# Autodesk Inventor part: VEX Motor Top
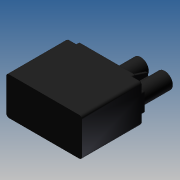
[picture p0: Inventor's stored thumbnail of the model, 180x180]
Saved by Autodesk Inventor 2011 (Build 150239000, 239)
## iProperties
Created: 2010-06
Part Number: VEX Motor Top
Document SubType Name: Modeling
Designer: Phil
Density: 1 g/cm^3
Author: Phil
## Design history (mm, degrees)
sketch "Sketch1"
  geometry: L1 (0, 20)-(37, 20); L2 (0, 0)-(37, 0); L3 (-1.5, 18.5)-(-1.5, 1.5); L4 (38.5, 1.5)-(38.5, 18.5); A1 r 1.5 centre (0, 18.5) between (0, 20) and (-1.5, 18.5); A2 r 1.5 centre (0, 1.5) between (-1.5, 1.5) and (0, 0); A3 r 1.5 centre (37, 1.5) between (37, 0) and (38.5, 1.5); A4 r 1.5 centre (37, 18.5) between (38.5, 18.5) and (37, 20); 2 further points
  constraints: 8 end point, 8 point on circle, 4 centre point
extrude "Extrusion1" new body sketch "Sketch1" distance "d0" = 33.4772; taper "d1" = 0 deg
sketch "Sketch2"
  geometry: L1 (-33.5, 2.5)-(-33.5, 0.5); L2 (-28, 4)-(-27.3, 4); L3 (-29.295, 9.35)-(-28.3, 9.35); L4 (-28.3, 4.315)-(-28.3, 9.35); L5 (-27, 9.35)-(-27, 4.315); L6 (-28.3, 10.65)-(-29.295, 10.65); L7 (-27, 9.35)-(-26.005, 9.35); L8 (-26.005, 10.65)-(-27, 10.65); L9 (-28.3, 10.65)-(-28.3, 15.685); L10 (-27.3, 16)-(-28, 16); L11 (-33.5, 0.5)-(-3.5, 0.5); L12 (-33.5, 19.5)-(-3.5, 19.5); L13 (-27, 15.685)-(-27, 10.65); L14 (-33.5, 20)-(-33.5, 17.5); L15 (-38, 5)-(-36, 5); L16 (-38, 7.438)-(-38, 5); L17 (-38, 15)-(-38, 12.562); L18 (-36, 15)-(-38.5, 15); L19 (-3.5, 0.5)-(-3.5, 2.5); L20 (-3.5, 17.5)-(-3.5, 19.5); L21 (-1, 5)-(1, 5); L22 (1, 5)-(1, 15); L23 (1, 15)-(-1, 15); L24 (-33.5, 20)-(-37, 20); L25 (-38.5, 18.5)-(-38.5, 15); C1 r 6.75 at (-8.6, 10); A1 r 1.5 centre (-37, 18.5) between (-37, 20) and (-38.5, 18.5); 2 further points
  constraints: 50 end point, 2 centre point, 2 point on circle, 2 point on line, 2 tangent, 1 parallel, 1 perpendicular, 29 other
extrude "Extrusion2" cut sketch "Sketch2" distance "d2" = 1.4986; taper "d3" = 0 deg
fillet "Fillet1" dims "d4" = 0.762
workplane "Work Plane1"
mirror "Mirror1"
workplane "Work Plane2"
mirror "Mirror2"
fillet "Fillet2" dims "d5" = 0.508
fillet "Fillet3" dims "d6" = 0.762
workplane "Work Plane4"
sketch "Sketch3"
  geometry: L1 (-38.5, 14.238)-(-38.5, 5.762) reference; L2 (-37.992, 5.762)-(-37.992, 14.238) reference; C1 r 4.255 at (-33.737, 10); C2 r 4.255 at (-21.037, 10); 2 further points
  constraints: 2 centre point, 2 horizontal alignment, 1 equal radius, 1 midpoint, 1 tangent
  dimensions: "d9" = 8.509 diameter of C1; "d10" = 12.7 distance of C2.centre C1.centre
extrude "Extrusion3" join sketch "Sketch3" stored distance "d11" = 9.525; taper "d12" = 0 deg
workplane "Work Plane5"
sketch "Sketch4"
  geometry: L1 (33.477, 16)-(33.477, 12.738) reference; L2 (33.477, 4.262)-(33.477, 1) reference; L3 (33.477, 14.494)-(45.466, 10.648); L4 (45.466, 10.648)-(45.466, 6.352); L5 (45.466, 6.352)-(33.477, 2.506); L6 (33.477, 14.494)-(33.477, 2.506); L7 (48.489, 12.755)-(48.489, 4.246) reference; 3 further points
  constraints: 8 end point, 2 midpoint, 2 parallel, 2 point on line, 1 horizontal alignment
  dimensions: "d14" = 11.9888 distance of L5.end L3.start; "d15" = 72.21 deg angle of L2 L5; "d16" = 72.21 deg angle of L1 L3; "d17" = 11.9888 distance between parallel lines of L6 L4
extrude "Extrusion4" join sketch "Sketch4" stored distance "d18" = 1.27; taper "d19" = 0 deg
sketch "Sketch5"
  geometry: L1 (0, 4.295)-(1.27, 4.295) reference; L2 (-1.46, 2.148)-(2.731, 2.148); 3 further points
  constraints: 2 end point, 2 horizontal alignment, 1 parallel, 2 other
feature "Rib1" sketch "Sketch5" dims "d20" = 1.27, "d21" = 2.54, "d22" = 0
fillet "Fillet4" dims "d23" = 0.508
fillet "Fillet5" dims "d24" = 0.254
sketch "Sketch6"
  geometry: C1 r 4.255 at (0, 0) reference; C2 r 4.255 at (12.7, 0) reference; 1 further point
hole "Hole1" sketch "Sketch6" at (0, 0), (12.7, 0) diameter "d25" = 5.5118; stored, may be unused: countersink angle "d29" = 82 deg, drill point angle "d31" = 118 deg; dims "d26" = 19.05, "d27" = 9.525, "d28" = 6.35, "d30" = 12.7
sketch "Sketch7"
  geometry: L1 (1.5, 5.762)-(1.5, 14.238) reference; C1 r 6.744 at (-8.609, 10); 1 further point
  constraints: 1 centre point
  dimensions: "d32" = 10.1092 distance from line of L1 C1.centre; "d33" = 13.4874 diameter of C1
extrude "Extrusion5" join sketch "Sketch7" distance "d34" = 1.5875; taper "d35" = -25 deg
sketch "Sketch8"
  geometry: 2 further points
hole "Hole2" sketch "Sketch8" at (-35.767, 17.185) diameter "d36" = 2.1082; stored, may be unused: countersink angle "d40" = 82 deg, drill point angle "d42" = 118 deg; dims "d37" = 19.05, "d38" = 9.525, "d39" = 6.35, "d41" = 3.175
pattern_linear "Rectangular Pattern1" dims "d45" = 34.29, "d48" = 14.478
body "Solid1"
node "Projected Loop1"
node "Projected Loop2"
node "Projected Loop3"
other parameters: "d8" = 15.0114, "d13" = -11.1125
